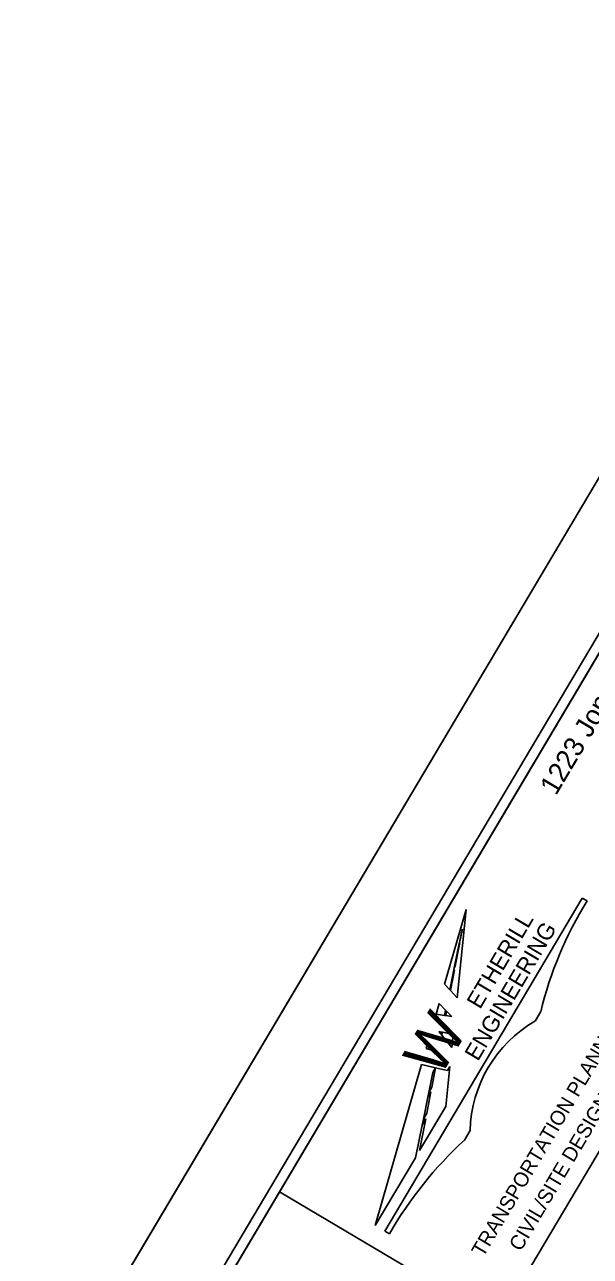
# Model space of a CAD drawing. Extents: x 2137081 to 2142019, y 404041 to 411238.
# Drawn here: x 2140819.3 to 2140961.3, y 410654.4 to 410963.6 of the extents above; entities that cross this region are included whole.
import ezdxf

# ---------------------------------------------------------------- set-up
doc = ezdxf.new("R2010")
doc.units = 0
for name, color, linetype in [('Default', 7, 'Continuous'), ('Sheet Clip Boundary CELL', 7, 'Continuous'), ('Sheet Cutting Line CELL', 7, 'Continuous'), ('Sheet Plan And Profile CELL', 7, 'Continuous'), ('Sheet Plot Border Inside CELL', 7, 'Continuous'), ('Sheet Plot Border Outside CELL', 7, 'Continuous')]:
    doc.layers.add(name, color=color, linetype=linetype)

msp = doc.modelspace()

# ---------------------------------------------------------------- linework, layer by layer
at = {"layer": 'Default'}
for p, q in [((2140909.68, 410660.69), (2140959.3, 410744.29)), ((2140959.3, 410744.29), (2140960.49, 410743.58)), ((2140930.14, 410741.41), (2140924.73, 410722.65)), ((2140930.14, 410741.41), (2140927.84, 410719.27)), ((2140929.99, 410740.72), (2140930.14, 410741.41)), ((2140930, 410740.74), (2140930.14, 410741.41)), ((2140928.53, 410733.55), (2140929.11, 410736.37)), ((2140928.66, 410733.78), (2140929.19, 410736.52)), ((2140927.14, 410726.75), (2140928.39, 410732.9)), ((2140927.38, 410727.17), (2140928.54, 410733.14)), ((2140928.53, 410733.55), (2140928.39, 410732.9)), ((2140928.39, 410732.9), (2140928.54, 410733.14)), ((2140928.66, 410733.78), (2140928.53, 410733.55)), ((2140927.14, 410726.75), (2140926.95, 410725.84)), ((2140927.38, 410727.17), (2140927.14, 410726.75)), ((2140926.01, 410721.26), (2140926.95, 410725.84)), ((2140926.2, 410721.05), (2140927.21, 410726.28)), ((2140926.95, 410725.84), (2140927.21, 410726.28)), ((2140924.73, 410722.65), (2140926.01, 410721.26)), ((2140926.2, 410721.05), (2140926.01, 410721.26)), ((2140927.84, 410719.27), (2140926.2, 410721.05)), ((2140922.58, 410715.17), (2140923.34, 410717.82)), ((2140924.96, 410716.14), (2140923.34, 410717.82)), ((2140922.58, 410715.17), (2140924.7, 410714.83)), ((2140924.7, 410714.83), (2140924.96, 410716.14)), ((2140925, 410714.78), (2140924.7, 410714.83)), ((2140925.21, 410715.89), (2140924.96, 410716.14)), ((2140925.21, 410715.89), (2140925, 410714.78)), ((2140925, 410714.78), (2140926.51, 410714.54)), ((2140926.51, 410714.54), (2140925.21, 410715.89)), ((2140948.84, 410715.78), (2140947.42, 410713.39)), ((2140923.28, 410710.78), (2140923.84, 410710.66)), ((2140923.75, 410710.21), (2140923.28, 410710.78)), ((2140923.84, 410710.66), (2140923.75, 410710.21)), ((2140923.75, 410710.21), (2140924.04, 410709.86)), ((2140923.84, 410710.66), (2140924.19, 410710.6)), ((2140924.04, 410709.86), (2140924.19, 410710.6)), ((2140926.55, 410706.82), (2140924.04, 410709.86)), ((2140924.19, 410710.6), (2140926.89, 410710.05)), ((2140926.89, 410710.05), (2140926.55, 410706.82)), ((2140920.09, 410706.54), (2140920.43, 410707.72)), ((2140921.71, 410706.05), (2140920.09, 410706.54)), ((2140920.43, 410707.72), (2140921.71, 410706.05)), ((2140907.29, 410662.11), (2140918.94, 410702.55)), ((2140918.94, 410702.55), (2140922.47, 410701.69)), ((2140921.53, 410696.83), (2140922.47, 410701.69)), ((2140921.53, 410696.83), (2140922.47, 410701.69)), ((2140922.47, 410701.69), (2140921.77, 410700.51)), ((2140922.47, 410701.69), (2140925.43, 410700.97)), ((2140926.05, 410702.01), (2140925.01, 410691.96)), ((2140925.43, 410700.97), (2140926.05, 410702.01)), ((2140920.74, 410695.51), (2140921.77, 410700.51)), ((2140920.27, 410690.34), (2140921.3, 410695.63)), ((2140920.49, 410694.28), (2140921.3, 410695.63)), ((2140920.74, 410695.51), (2140920.49, 410694.28)), ((2140921.53, 410696.83), (2140920.74, 410695.51)), ((2140919.38, 410688.82), (2140920.49, 410694.28)), ((2140925.01, 410691.96), (2140918.45, 410680.92)), ((2140920.27, 410690.34), (2140919.38, 410688.82)), ((2140917.39, 410679.12), (2140919.07, 410687.31)), ((2140918.45, 410680.92), (2140919.99, 410688.87)), ((2140919.07, 410687.31), (2140919.99, 410688.87)), ((2140919.99, 410688.87), (2140919.07, 410687.31)), ((2140919.07, 410687.31), (2140919.99, 410688.87)), ((2140919.38, 410688.82), (2140919.07, 410687.31)), ((2140931.11, 410685.92), (2140929.7, 410683.53)), ((2140917.39, 410679.12), (2140907.29, 410662.11)), ((2140910.87, 410659.98), (2140909.68, 410660.69))]:
    msp.add_line(p, q, dxfattribs=at)
msp.add_lwpolyline([(2140883.25, 410670.58), (2140985.54, 410842.92), (2141040.49, 410810.3), (2140938.2, 410637.97)], close=True, dxfattribs=at)
for centre, radius, start, end in [((2141042.59, 410692.81), 96.52, 148.2658, 166.2364), ((2140963.8, 410685.09), 32.7, 120.0727, 178.546), ((2140997.37, 410610.15), 99.83, 132.6813, 150.0525)]:
    msp.add_arc(centre, radius, start, end, dxfattribs=at)
at = {"layer": 'Sheet Clip Boundary CELL'}
msp.add_lwpolyline([(2140795, 409444.32), (2141473.2, 410586.96), (2141453.94, 410598.39), (2141513.05, 410697.97), (2141213, 410886.12), (2141134.78, 410754.33), (2141040.49, 410810.3), (2140938.2, 410637.97), (2140883.25, 410670.58), (2140322.04, 409725.04)], close=True, dxfattribs=at)
at = {"layer": 'Sheet Cutting Line CELL'}
msp.add_line((2141076.97, 411041.05), (2140217.7, 409593.35), dxfattribs=at)
at = {"layer": 'Sheet Plan And Profile CELL'}
msp.add_lwpolyline([(2141087.64, 411014.95), (2140322.04, 409725.04), (2141224.97, 409189.12), (2141990.57, 410479.02)], close=True, dxfattribs=at)
at = {"layer": 'Sheet Plot Border Inside CELL'}
msp.add_lwpolyline([(2141148.77, 409055.84), (2141999.1, 410488.49), (2141091.87, 411026.97), (2140241.54, 409594.32)], close=True, dxfattribs=at)
at = {"layer": 'Sheet Plot Border Outside CELL'}
msp.add_lwpolyline([(2141159.33, 409034.46), (2142018.6, 410482.16), (2141076.97, 411041.05), (2140217.7, 409593.35)], close=True, dxfattribs=at)

# ---------------------------------------------------------------- texts
at = {"layer": 'Default'}
for s, height, p in [('1223 Jones Franklin Rd.', 5.01, (2140952.68, 410769.83)), ('TRANSPORTATION PLANNING/DESIGN - BRIDGE/STRUCTURE DESIGN', 3.674, (2140934.41, 410653.94)), ('CIVIL/SITE DESIGN - GIS/GPS - CONSTRUCTION OBSERVATION', 3.674, (2140943.82, 410655.39)), ('ETHERILL', 4.167, (2140933.61, 410716.19)), ('ENGINEERING', 4.1665, (2140933.08, 410703.14)), ('W', 11.11, (2140923.48, 410698.99))]:
    msp.add_text(s, height=height, rotation=59.3093, dxfattribs=at).set_placement(p)

doc.saveas('drawing.dxf')
